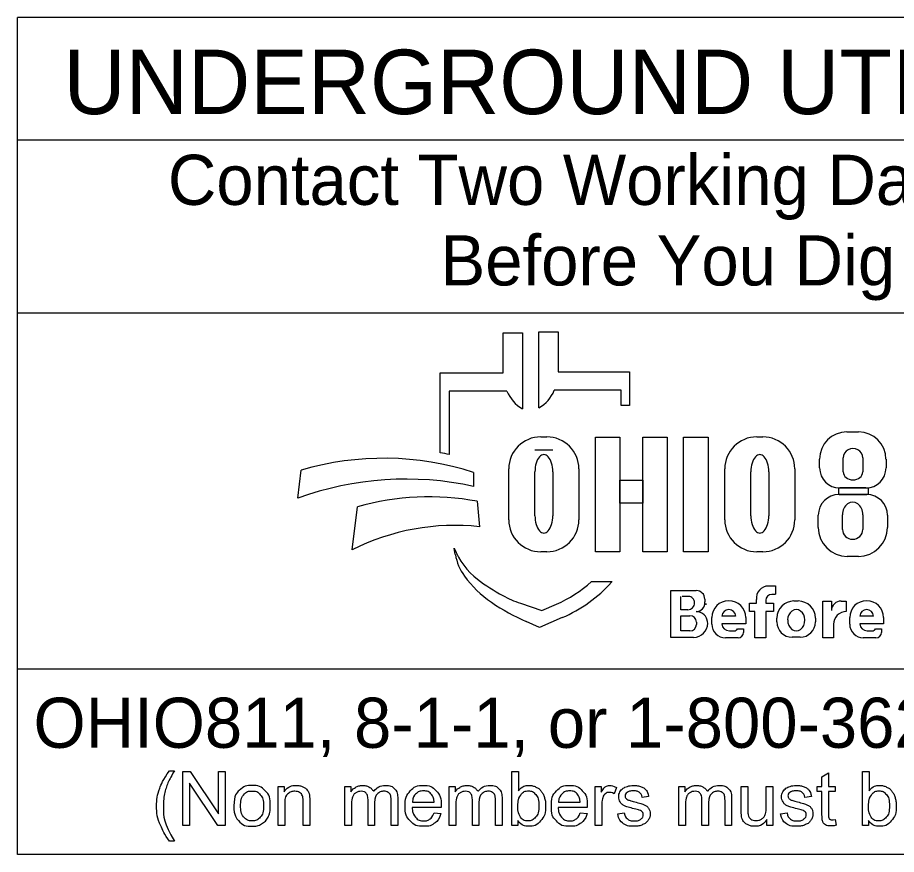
# Model space of a CAD drawing. Extents: x 0 to 34, y -7.5 to 22.
# Drawn here: x 2.378 to 4.831, y 2.143 to 4.48 of the extents above; entities that cross this region are included whole.
import ezdxf

# ---------------------------------------------------------------- set-up
doc = ezdxf.new("R2010")
doc.units = 0
doc.layers.add('SH_Data', color=7, linetype='Continuous')
doc.layers.add('SH_Text', color=7, linetype='Continuous')

msp = doc.modelspace()

# ---------------------------------------------------------------- linework, layer by layer
at = {"layer": 'SH_Data'}
for p, q in [((2.3775, 2.1428), (2.3775, 4.4803)), ((6.6275, 4.4803), (2.3775, 4.4803)), ((2.3775, 4.1387), (6.6275, 4.1387)), ((2.3775, 3.6553), (6.6275, 3.6553)), ((6.6275, 2.6607), (2.3775, 2.6607)), ((6.6275, 2.1428), (2.3775, 2.1428))]:
    msp.add_line(p, q, dxfattribs=at)
at = {"layer": 'SH_Text'}
for p, q in [((3.7335, 3.4883), (3.7335, 3.5998)), ((3.7335, 3.5998), (3.7872, 3.5998)), ((3.7872, 3.5998), (3.7872, 3.3877)), ((3.8329, 3.39), (3.8329, 3.6021)), ((3.8329, 3.6021), (3.8865, 3.6021)), ((3.8865, 3.6021), (3.8865, 3.4906)), ((3.5576, 3.2644), (3.5576, 3.4883)), ((3.5576, 3.4883), (3.7335, 3.4883)), ((3.8865, 3.4906), (4.0857, 3.4906)), ((4.0857, 3.4906), (4.0857, 3.3968)), ((3.5828, 3.4369), (3.5828, 3.26)), ((3.7439, 3.4369), (3.5828, 3.4369)), ((4.0625, 3.4392), (3.8761, 3.4392)), ((4.0625, 3.3968), (4.0625, 3.4392)), ((4.0857, 3.3968), (4.0625, 3.3968)), ((4.6931, 3.3231), (4.7258, 3.3231)), ((3.8385, 3.3091), (3.8551, 3.3091)), ((4.4416, 3.3091), (4.4581, 3.3091)), ((3.8718, 3.2721), (3.822, 3.2721)), ((4.6168, 3.2225), (4.6168, 3.2468)), ((4.683, 3.2111), (4.683, 3.2504)), ((4.7371, 3.2504), (4.7371, 3.2111)), ((4.8022, 3.2468), (4.8022, 3.2225)), ((3.1602, 3.1381), (3.1696, 3.2162)), ((3.7491, 3.0776), (3.7491, 3.2196)), ((3.9445, 3.2196), (3.9445, 3.0776)), ((4.3521, 3.0776), (4.3521, 3.2196)), ((4.5476, 3.2196), (4.5476, 3.0776)), ((3.6509, 3.2097), (3.6509, 3.1709)), ((3.822, 3.089), (3.822, 3.2114)), ((3.8718, 3.2114), (3.8718, 3.089)), ((4.425, 3.089), (4.425, 3.2114)), ((4.4748, 3.2114), (4.4748, 3.089)), ((4.7462, 3.1665), (4.6728, 3.1665)), ((4.671, 3.1482), (4.7483, 3.1482)), ((3.6608, 3.1291), (3.6671, 3.0582)), ((3.312, 2.9936), (3.3267, 3.1137)), ((4.6131, 3.0563), (4.6131, 3.0903)), ((4.6806, 3.0503), (4.6806, 3.0912)), ((4.7374, 3.0912), (4.7374, 3.0503)), ((4.8062, 3.0903), (4.8062, 3.0563)), ((3.5997, 2.9807), (3.5967, 2.9986)), ((3.8551, 2.9882), (3.8385, 2.9882)), ((4.4581, 2.9882), (4.4416, 2.9882)), ((4.7252, 2.9753), (4.6941, 2.9753)), ((3.98, 2.9048), (4.0375, 2.9048)), ((4.2013, 2.749), (4.2013, 2.8798)), ((4.2013, 2.8798), (4.2725, 2.8798)), ((4.4739, 2.8926), (4.4934, 2.8926)), ((4.4934, 2.8926), (4.4934, 2.8696)), ((4.2293, 2.8263), (4.2293, 2.8632)), ((4.2545, 2.8632), (4.2332, 2.8632)), ((4.2963, 2.856), (4.2963, 2.8481)), ((4.4406, 2.8442), (4.4406, 2.8546)), ((4.4667, 2.8526), (4.4667, 2.8442)), ((4.4934, 2.8691), (4.4832, 2.8691)), ((4.5451, 2.8508), (4.5573, 2.8508)), ((4.6254, 2.7478), (4.6254, 2.8505)), ((4.6254, 2.8505), (4.6499, 2.8505)), ((4.6499, 2.8505), (4.6499, 2.8237)), ((4.6772, 2.8505), (4.691, 2.8505)), ((4.691, 2.8505), (4.691, 2.8209)), ((3.7816, 2.8444), (3.841, 2.8239)), ((3.841, 2.8239), (3.8821, 2.8417)), ((4.2487, 2.8263), (4.2293, 2.8263)), ((4.4213, 2.8212), (4.4213, 2.8442)), ((4.4213, 2.8442), (4.4406, 2.8442)), ((4.4667, 2.8442), (4.4883, 2.8442)), ((4.4883, 2.8442), (4.4883, 2.8212)), ((3.8983, 2.8044), (3.835, 2.7769)), ((4.2293, 2.7669), (4.2293, 2.8097)), ((4.2293, 2.8097), (4.2548, 2.8097)), ((4.3159, 2.7858), (4.3159, 2.8042)), ((4.3824, 2.8082), (4.3439, 2.8082)), ((4.4104, 2.8042), (4.4104, 2.7866)), ((4.4362, 2.8212), (4.4213, 2.8212)), ((4.4362, 2.7478), (4.4362, 2.8212)), ((4.4883, 2.8212), (4.4667, 2.8212)), ((4.4667, 2.8212), (4.4667, 2.7478)), ((4.4973, 2.7922), (4.4973, 2.8029)), ((4.6051, 2.8029), (4.6051, 2.7922)), ((4.7008, 2.7858), (4.7008, 2.8042)), ((4.7674, 2.8082), (4.7288, 2.8082)), ((4.7953, 2.8042), (4.7953, 2.7866)), ((3.835, 2.7769), (3.7976, 2.7934)), ((4.2729, 2.7916), (4.2729, 2.7853)), ((4.3043, 2.7887), (4.3043, 2.7884)), ((4.4104, 2.7866), (4.344, 2.7866)), ((4.3876, 2.7729), (4.4045, 2.7729)), ((4.4045, 2.7729), (4.4045, 2.7631)), ((4.6559, 2.786), (4.6559, 2.7478)), ((4.7953, 2.7866), (4.7289, 2.7866)), ((4.7725, 2.7729), (4.7894, 2.7729)), ((4.7894, 2.7729), (4.7894, 2.7631)), ((4.265, 2.749), (4.2013, 2.749)), ((4.2546, 2.7669), (4.2293, 2.7669)), ((4.3649, 2.7673), (4.379, 2.7673)), ((4.5623, 2.7494), (4.5401, 2.7494)), ((4.7498, 2.7673), (4.7639, 2.7673)), ((4.3892, 2.7478), (4.3538, 2.7478)), ((4.4667, 2.7478), (4.4362, 2.7478)), ((4.6559, 2.7478), (4.6254, 2.7478)), ((4.7742, 2.7478), (4.7388, 2.7478))]:
    msp.add_line(p, q, dxfattribs=at)
for points in [[(3.991, 3.3081), (4.0589, 3.3081), (4.0589, 2.9881), (3.991, 2.9881)], [(4.1231, 3.3081), (4.1911, 3.3081), (4.1911, 2.9881), (4.1231, 2.9881)], [(4.2364, 3.3081), (4.3052, 3.3081), (4.3052, 2.9881), (4.2364, 2.9881)], [(4.0589, 3.1882), (4.1231, 3.1882), (4.1231, 3.1242), (4.0589, 3.1242)], [(4.6706, 3.1665), (4.7523, 3.1665), (4.7523, 3.1481), (4.6706, 3.1481)]]:
    msp.add_lwpolyline(points, close=True, dxfattribs=at)
for points in [[(2.8021, 2.3766), (2.8153, 2.3766)], [(2.8389, 2.2239), (2.8389, 2.3741), (2.8592, 2.3741), (2.9382, 2.2561), (2.9382, 2.3741), (2.9572, 2.3741), (2.9572, 2.2239), (2.9369, 2.2239), (2.8579, 2.3419), (2.8579, 2.2239), (2.8389, 2.2239)], [(3.7743, 2.2239), (3.7573, 2.2239), (3.7573, 2.3741), (3.7757, 2.3741), (3.7757, 2.3206)], [(4.6233, 2.2558), (4.6233, 2.3185), (4.6097, 2.3185), (4.6097, 2.3328), (4.6233, 2.3328), (4.6233, 2.3597), (4.6417, 2.3708), (4.6417, 2.3328), (4.6601, 2.3328), (4.6601, 2.3185), (4.6417, 2.3185), (4.6417, 2.2547)], [(4.7534, 2.2239), (4.7363, 2.2239), (4.7363, 2.3741), (4.7548, 2.3741), (4.7548, 2.3206)], [(3.1048, 2.2239), (3.1048, 2.3328), (3.1214, 2.3328), (3.1214, 2.3173)], [(3.2912, 2.2239), (3.2912, 2.3328), (3.3077, 2.3328), (3.3077, 2.3174)], [(3.5826, 2.2239), (3.5826, 2.3328), (3.5991, 2.3328), (3.5991, 2.3174)], [(3.9904, 2.2239), (3.9904, 2.3328), (4.007, 2.3328), (4.007, 2.3163)], [(4.2236, 2.2239), (4.2236, 2.3328), (4.2401, 2.3328), (4.2401, 2.3174)], [(4.3979, 2.2654), (4.3979, 2.3328), (4.4164, 2.3328), (4.4164, 2.2724)], [(4.4676, 2.2745), (4.4676, 2.3328), (4.4861, 2.3328), (4.4861, 2.2239), (4.4696, 2.2239)], [(4.0495, 2.3293), (4.043, 2.3122)], [(3.1233, 2.2833), (3.1233, 2.2239), (3.1048, 2.2239)], [(3.1932, 2.2908), (3.1932, 2.2239), (3.1748, 2.2239), (3.1748, 2.2901)], [(3.3743, 2.2871), (3.3743, 2.2239), (3.3559, 2.2239), (3.3559, 2.2946)], [(3.4388, 2.2986), (3.4388, 2.2239), (3.4203, 2.2239), (3.4203, 2.2924)], [(3.4799, 2.2887), (3.5406, 2.2887)], [(3.6657, 2.2871), (3.6657, 2.2239), (3.6473, 2.2239), (3.6473, 2.2946)], [(3.7301, 2.2986), (3.7301, 2.2239), (3.7117, 2.2239), (3.7117, 2.2924)], [(3.8879, 2.2887), (3.9486, 2.2887)], [(4.1394, 2.3046), (4.1213, 2.3022)], [(4.3067, 2.2871), (4.3067, 2.2239), (4.2883, 2.2239), (4.2883, 2.2946)], [(4.3711, 2.2986), (4.3711, 2.2239), (4.3527, 2.2239), (4.3527, 2.2924)], [(4.594, 2.3046), (4.5759, 2.3022)], [(3.3097, 2.2803), (3.3097, 2.2239), (3.2912, 2.2239)], [(3.56, 2.2736), (3.4788, 2.2736)], [(3.5404, 2.2591), (3.5595, 2.2567)], [(3.601, 2.2803), (3.601, 2.2239), (3.5826, 2.2239)], [(3.968, 2.2736), (3.8868, 2.2736)], [(3.9484, 2.2591), (3.9675, 2.2567)], [(4.0088, 2.2809), (4.0088, 2.2239), (3.9904, 2.2239)], [(4.053, 2.2564), (4.0712, 2.2593)], [(4.242, 2.2803), (4.242, 2.2239), (4.2236, 2.2239)], [(4.5076, 2.2564), (4.5258, 2.2593)], [(3.7743, 2.2375), (3.7743, 2.2239)], [(4.4696, 2.2239), (4.4696, 2.24)], [(4.6601, 2.2404), (4.6628, 2.2241)], [(4.7534, 2.2375), (4.7534, 2.2239)], [(2.8153, 2.1798), (2.8021, 2.1798)]]:
    msp.add_lwpolyline(points, dxfattribs=at)
for centre, radius, start, end in [((3.8353, 3.4736), 0.0985, 201.9296, 240.7469), ((3.7847, 3.476), 0.0985, 299.2531, 338.0704), ((4.6931, 3.2468), 0.0763, 90, 180), ((4.7258, 3.2468), 0.0763, 0, 90), ((3.8385, 3.2196), 0.0895, 90, 180), ((3.8551, 3.2196), 0.0895, 0, 90), ((4.4416, 3.2196), 0.0895, 90, 180), ((4.4581, 3.2196), 0.0895, 0, 90), ((3.4295, 2.4554), 0.8191, 79.2074, 81.0007), ((3.3997, 2.4302), 0.8191, 72.1402, 106.3144), ((4.6728, 3.2225), 0.056, 180, 270), ((4.7462, 3.2225), 0.056, 270, 0), ((3.4628, 2.2991), 0.8919, 77.8238, 109.8274), ((3.5267, 2.4094), 0.7322, 79.44, 105.8467), ((4.671, 3.0903), 0.0579, 90, 180), ((4.7483, 3.0903), 0.0579, 0, 90), ((3.8385, 3.0776), 0.0895, 180, 270), ((3.8551, 3.0776), 0.0895, 270, 0), ((4.4416, 3.0776), 0.0895, 180, 270), ((4.4581, 3.0776), 0.0895, 270, 0), ((3.5987, 2.4262), 0.6357, 83.8248, 116.8021), ((4.6941, 3.0563), 0.081, 180, 270), ((4.7252, 3.0563), 0.081, 270, 0), ((3.7841, 3.0707), 0.2008, 201.0457, 232.5314), ((3.741, 3.0048), 0.1433, 189.6817, 216.0884), ((3.8747, 3.1022), 0.3088, 216.0884, 235.7167), ((3.9766, 3.3219), 0.5173, 232.5314, 241.794), ((3.7387, 3.1722), 0.3602, 293.4582, 312.0712), ((3.7387, 3.1722), 0.401, 293.4582, 317.8286), ((4.2725, 2.856), 0.0238, 0, 90), ((4.4739, 2.859), 0.0335, 90, 187.5187), ((4.0412, 3.3465), 0.6044, 235.7167, 246.2325), ((3.8914, 3.1631), 0.3371, 241.794, 250.9821), ((4.2505, 2.8463), 0.0169, 357.8325, 90), ((4.2721, 2.8453), 0.0243, 270, 6.6529), ((4.3631, 2.8042), 0.0473, 0, 180), ((4.4832, 2.8526), 0.0165, 90, 180), ((4.5451, 2.8029), 0.0478, 90, 180), ((4.5573, 2.8029), 0.0478, 0, 90), ((4.6768, 2.8237), 0.0269, 89.2449, 180), ((4.7481, 2.8042), 0.0473, 0, 180), ((4.2487, 2.845), 0.0187, 270, 2.0582), ((4.2827, 2.8438), 0.0175, 347.4023, 0), ((4.3632, 2.8072), 0.0193, 2.9632, 177.0368), ((4.7481, 2.8072), 0.0193, 2.9632, 177.0368), ((4.2548, 2.7916), 0.0181, 0, 90), ((4.2722, 2.7889), 0.0321, 4.0748, 90), ((4.6908, 2.786), 0.0349, 89.6033, 180), ((4.2546, 2.7853), 0.0184, 270, 0), ((4.265, 2.7884), 0.0393, 270, 0), ((4.2714, 2.7887), 0.033, 0, 11.7502), ((4.3538, 2.7858), 0.038, 180, 270), ((4.3649, 2.7883), 0.021, 184.827, 270), ((4.379, 2.7767), 0.00938, 270, 335.9979), ((4.5401, 2.7922), 0.0428, 180, 270), ((4.5623, 2.7922), 0.0428, 270, 0), ((4.7388, 2.7858), 0.038, 180, 270), ((4.7498, 2.7883), 0.021, 184.827, 270), ((4.7639, 2.7767), 0.00938, 270, 335.9979), ((4.3892, 2.7631), 0.0152, 270, 0), ((4.7742, 2.7631), 0.0152, 270, 0)]:
    msp.add_arc(centre, radius, start, end, dxfattribs=at)
for centre, major_axis, ratio, start_param, end_param in [((4.71, 3.2504), (0.0271, 0), 0.969373, 0, 3.141593), ((3.8469, 3.2114), (0, 0.0484), 0.514403, 4.712389, 7.853982), ((4.4499, 3.2114), (0, 0.0484), 0.514403, 4.712389, 7.853982), ((4.71, 3.2111), (0.0271, 0), 0.818453, 3.141593, 6.283185), ((4.709, 3.0912), (0, 0.0358), 0.794529, 4.712389, 7.853982), ((3.8469, 3.089), (0, 0.0484), 0.514403, 1.570796, 4.712389), ((4.4499, 3.089), (0, 0.0484), 0.514403, 1.570796, 4.712389), ((4.709, 3.0503), (0.0284, 0), 0.959837, 3.141593, 6.283185), ((4.5517, 2.7976), (0, 0.029), 0.832186, 4.712389, 7.853982), ((4.5517, 2.7976), (0, 0.0302), 0.797287, 1.570796, 4.712389)]:
    msp.add_ellipse(centre, major_axis=major_axis, ratio=ratio, start_param=start_param, end_param=end_param, dxfattribs=at)
for points in [[(2.8021, 2.1798), (2.7869, 2.199), (2.7763, 2.2248), (2.7657, 2.2506), (2.7657, 2.2783), (2.7657, 2.3026), (2.7736, 2.325), (2.7829, 2.3509), (2.8021, 2.3766)], [(2.8153, 2.3766), (2.8029, 2.3553), (2.7989, 2.3462), (2.7927, 2.332), (2.7891, 2.3167), (2.7847, 2.2975), (2.7847, 2.2782), (2.7847, 2.2289), (2.8153, 2.1798)], [(2.9814, 2.2783), (2.9814, 2.3085), (2.9981, 2.3231), (3.0122, 2.3352), (3.0323, 2.3352), (3.0547, 2.3352), (3.069, 2.3205), (3.0832, 2.3058), (3.0832, 2.2799), (3.0832, 2.2589), (3.0769, 2.2469), (3.0706, 2.2348), (3.0586, 2.2282), (3.0466, 2.2215), (3.0323, 2.2215), (3.0095, 2.2215), (2.9954, 2.2362), (2.9814, 2.2508), (2.9814, 2.2783)], [(3.1214, 2.3173), (3.1334, 2.3352), (3.156, 2.3352), (3.1659, 2.3352), (3.1741, 2.3316), (3.1823, 2.3281), (3.1864, 2.3224), (3.1905, 2.3166), (3.1922, 2.3087), (3.1932, 2.3036), (3.1932, 2.2908)], [(3.3077, 2.3174), (3.3128, 2.3254), (3.3214, 2.3303), (3.3299, 2.3352), (3.3407, 2.3352), (3.3528, 2.3352), (3.3606, 2.3301), (3.3683, 2.3251), (3.3715, 2.3161), (3.3844, 2.3352), (3.4051, 2.3352), (3.4213, 2.3352), (3.43, 2.3262), (3.4388, 2.3172), (3.4388, 2.2986)], [(3.5595, 2.2567), (3.555, 2.24), (3.5428, 2.2307), (3.5306, 2.2215), (3.5117, 2.2215), (3.4878, 2.2215), (3.4738, 2.2362), (3.4598, 2.2509), (3.4598, 2.2774), (3.4598, 2.3049), (3.474, 2.32), (3.4881, 2.3352), (3.5106, 2.3352), (3.5324, 2.3352), (3.5463, 2.3203), (3.5601, 2.3055), (3.5601, 2.2785), (3.5601, 2.2769), (3.56, 2.2736)], [(3.5991, 2.3174), (3.6042, 2.3254), (3.6127, 2.3303), (3.6212, 2.3352), (3.6321, 2.3352), (3.6442, 2.3352), (3.6519, 2.3301), (3.6597, 2.3251), (3.6628, 2.3161), (3.6758, 2.3352), (3.6965, 2.3352), (3.7127, 2.3352), (3.7214, 2.3262), (3.7301, 2.3172), (3.7301, 2.2986)], [(3.7757, 2.3206), (3.7874, 2.3352), (3.8055, 2.3352), (3.8155, 2.3352), (3.8245, 2.3311), (3.8335, 2.3271), (3.8392, 2.3198), (3.845, 2.3124), (3.8483, 2.3021), (3.8516, 2.2918), (3.8516, 2.28), (3.8516, 2.252), (3.8378, 2.2368), (3.8239, 2.2215), (3.8046, 2.2215), (3.7853, 2.2215), (3.7743, 2.2375)], [(3.9675, 2.2567), (3.963, 2.24), (3.9508, 2.2307), (3.9386, 2.2215), (3.9196, 2.2215), (3.8958, 2.2215), (3.8818, 2.2362), (3.8678, 2.2509), (3.8678, 2.2774), (3.8678, 2.3049), (3.882, 2.32), (3.8961, 2.3352), (3.9186, 2.3352), (3.9404, 2.3352), (3.9543, 2.3203), (3.9681, 2.3055), (3.9681, 2.2785), (3.9681, 2.2769), (3.968, 2.2736)], [(4.007, 2.3163), (4.0133, 2.3278), (4.0187, 2.3315), (4.0241, 2.3352), (4.0305, 2.3352), (4.0398, 2.3352), (4.0495, 2.3293)], [(4.0712, 2.2593), (4.0727, 2.2483), (4.0798, 2.2425), (4.0868, 2.2366), (4.0995, 2.2366), (4.1122, 2.2366), (4.1184, 2.2418), (4.1245, 2.247), (4.1245, 2.254), (4.1245, 2.2602), (4.1191, 2.2638), (4.1153, 2.2663), (4.1002, 2.2701), (4.0799, 2.2752), (4.072, 2.2789), (4.0642, 2.2827), (4.0601, 2.2893), (4.0561, 2.2959), (4.0561, 2.3038), (4.0561, 2.3111), (4.0594, 2.3173), (4.0628, 2.3235), (4.0685, 2.3276), (4.0728, 2.3308), (4.0803, 2.333), (4.0877, 2.3352), (4.0962, 2.3352), (4.109, 2.3352), (4.1187, 2.3315), (4.1284, 2.3278), (4.133, 2.3215), (4.1377, 2.3152), (4.1394, 2.3046)], [(4.2401, 2.3174), (4.2452, 2.3254), (4.2537, 2.3303), (4.2622, 2.3352), (4.2731, 2.3352), (4.2852, 2.3352), (4.2929, 2.3301), (4.3007, 2.3251), (4.3038, 2.3161), (4.3168, 2.3352), (4.3375, 2.3352), (4.3537, 2.3352), (4.3624, 2.3262), (4.3711, 2.3172), (4.3711, 2.2986)], [(4.5258, 2.2593), (4.5273, 2.2483), (4.5343, 2.2425), (4.5414, 2.2366), (4.554, 2.2366), (4.5668, 2.2366), (4.5729, 2.2418), (4.5791, 2.247), (4.5791, 2.254), (4.5791, 2.2602), (4.5736, 2.2638), (4.5698, 2.2663), (4.5548, 2.2701), (4.5345, 2.2752), (4.5266, 2.2789), (4.5188, 2.2827), (4.5147, 2.2893), (4.5107, 2.2959), (4.5107, 2.3038), (4.5107, 2.3111), (4.514, 2.3173), (4.5173, 2.3235), (4.5231, 2.3276), (4.5274, 2.3308), (4.5348, 2.333), (4.5423, 2.3352), (4.5508, 2.3352), (4.5636, 2.3352), (4.5733, 2.3315), (4.583, 2.3278), (4.5876, 2.3215), (4.5922, 2.3152), (4.594, 2.3046)], [(4.7548, 2.3206), (4.7664, 2.3352), (4.7846, 2.3352), (4.7946, 2.3352), (4.8036, 2.3311), (4.8125, 2.3271), (4.8183, 2.3198), (4.8241, 2.3124), (4.8274, 2.3021), (4.8306, 2.2918), (4.8306, 2.28), (4.8306, 2.252), (4.8168, 2.2368), (4.803, 2.2215), (4.7836, 2.2215), (4.7644, 2.2215), (4.7534, 2.2375)], [(3.0003, 2.2783), (3.0003, 2.2574), (3.0094, 2.247), (3.0185, 2.2366), (3.0323, 2.2366), (3.046, 2.2366), (3.0551, 2.2471), (3.0642, 2.2575), (3.0642, 2.279), (3.0642, 2.2991), (3.0551, 2.3095), (3.0459, 2.3199), (3.0323, 2.3199), (3.0185, 2.3199), (3.0094, 2.3096), (3.0003, 2.2992), (3.0003, 2.2783)], [(3.1748, 2.2901), (3.1748, 2.3013), (3.1726, 2.3069), (3.1705, 2.3125), (3.165, 2.3158), (3.1595, 2.3191), (3.1521, 2.3191), (3.1404, 2.3191), (3.1318, 2.3117), (3.1233, 2.3042), (3.1233, 2.2833)], [(3.3559, 2.2946), (3.3559, 2.3069), (3.3514, 2.313), (3.3469, 2.3191), (3.3366, 2.3191), (3.3288, 2.3191), (3.3222, 2.315), (3.3156, 2.311), (3.3126, 2.3031), (3.3097, 2.2952), (3.3097, 2.2803)], [(3.4203, 2.2924), (3.4203, 2.3035), (3.4185, 2.3083), (3.4168, 2.3132), (3.412, 2.3162), (3.4073, 2.3191), (3.401, 2.3191), (3.3895, 2.3191), (3.3819, 2.3115), (3.3743, 2.3039), (3.3743, 2.2871)], [(3.5406, 2.2887), (3.5394, 2.3025), (3.5337, 2.3094), (3.5249, 2.3201), (3.5108, 2.3201), (3.4981, 2.3201), (3.4894, 2.3115), (3.4808, 2.303), (3.4799, 2.2887)], [(3.6473, 2.2946), (3.6473, 2.3069), (3.6428, 2.313), (3.6383, 2.3191), (3.628, 2.3191), (3.6202, 2.3191), (3.6136, 2.315), (3.607, 2.311), (3.604, 2.3031), (3.601, 2.2952), (3.601, 2.2803)], [(3.7117, 2.2924), (3.7117, 2.3035), (3.7099, 2.3083), (3.7081, 2.3132), (3.7034, 2.3162), (3.6987, 2.3191), (3.6923, 2.3191), (3.6809, 2.3191), (3.6733, 2.3115), (3.6657, 2.3039), (3.6657, 2.2871)], [(3.7741, 2.2792), (3.7741, 2.2596), (3.7794, 2.2509), (3.7881, 2.2366), (3.8029, 2.2366), (3.815, 2.2366), (3.8238, 2.2471), (3.8326, 2.2576), (3.8326, 2.2784), (3.8326, 2.2998), (3.8241, 2.3099), (3.8157, 2.3201), (3.8038, 2.3201), (3.7917, 2.3201), (3.7829, 2.3096), (3.7741, 2.299), (3.7741, 2.2792)], [(3.9486, 2.2887), (3.9474, 2.3025), (3.9417, 2.3094), (3.9328, 2.3201), (3.9188, 2.3201), (3.9061, 2.3201), (3.8974, 2.3115), (3.8888, 2.303), (3.8879, 2.2887)], [(4.043, 2.3122), (4.0363, 2.3162), (4.0295, 2.3162), (4.0235, 2.3162), (4.0187, 2.3125), (4.0139, 2.3089), (4.0119, 2.3024), (4.0088, 2.2926), (4.0088, 2.2809)], [(4.1213, 2.3022), (4.1201, 2.3106), (4.1142, 2.3153), (4.1083, 2.3201), (4.0975, 2.3201), (4.0848, 2.3201), (4.0794, 2.3159), (4.0739, 2.3116), (4.0739, 2.306), (4.0739, 2.3024), (4.0762, 2.2995), (4.0785, 2.2966), (4.0833, 2.2946), (4.086, 2.2936), (4.0996, 2.2899), (4.1192, 2.2847), (4.1269, 2.2813), (4.1347, 2.278), (4.1391, 2.2717), (4.1435, 2.2653), (4.1435, 2.2559), (4.1435, 2.2467), (4.1381, 2.2386), (4.1327, 2.2304), (4.1226, 2.226), (4.1124, 2.2215), (4.0996, 2.2215), (4.0784, 2.2215), (4.0672, 2.2303), (4.0561, 2.2391), (4.053, 2.2564)], [(4.2883, 2.2946), (4.2883, 2.3069), (4.2838, 2.313), (4.2793, 2.3191), (4.269, 2.3191), (4.2612, 2.3191), (4.2546, 2.315), (4.248, 2.311), (4.245, 2.3031), (4.242, 2.2952), (4.242, 2.2803)], [(4.3527, 2.2924), (4.3527, 2.3035), (4.3509, 2.3083), (4.3491, 2.3132), (4.3444, 2.3162), (4.3397, 2.3191), (4.3333, 2.3191), (4.3219, 2.3191), (4.3143, 2.3115), (4.3067, 2.3039), (4.3067, 2.2871)], [(4.5759, 2.3022), (4.5747, 2.3106), (4.5688, 2.3153), (4.5629, 2.3201), (4.5521, 2.3201), (4.5394, 2.3201), (4.5339, 2.3159), (4.5285, 2.3116), (4.5285, 2.306), (4.5285, 2.3024), (4.5308, 2.2995), (4.533, 2.2966), (4.5378, 2.2946), (4.5406, 2.2936), (4.5542, 2.2899), (4.5737, 2.2847), (4.5815, 2.2813), (4.5893, 2.278), (4.5937, 2.2717), (4.5981, 2.2653), (4.5981, 2.2559), (4.5981, 2.2467), (4.5927, 2.2386), (4.5873, 2.2304), (4.5772, 2.226), (4.567, 2.2215), (4.5542, 2.2215), (4.5329, 2.2215), (4.5218, 2.2303), (4.5107, 2.2391), (4.5076, 2.2564)], [(4.7532, 2.2792), (4.7532, 2.2596), (4.7585, 2.2509), (4.7672, 2.2366), (4.782, 2.2366), (4.7941, 2.2366), (4.8029, 2.2471), (4.8116, 2.2576), (4.8116, 2.2784), (4.8116, 2.2998), (4.8032, 2.3099), (4.7948, 2.3201), (4.7828, 2.3201), (4.7708, 2.3201), (4.762, 2.3096), (4.7532, 2.299), (4.7532, 2.2792)], [(3.4788, 2.2736), (3.4799, 2.2557), (3.489, 2.2462), (3.4981, 2.2366), (3.5117, 2.2366), (3.5219, 2.2366), (3.5291, 2.242), (3.5362, 2.2473), (3.5404, 2.2591)], [(3.8868, 2.2736), (3.8879, 2.2557), (3.897, 2.2462), (3.9061, 2.2366), (3.9197, 2.2366), (3.9299, 2.2366), (3.937, 2.242), (3.9442, 2.2473), (3.9484, 2.2591)], [(4.4696, 2.24), (4.4569, 2.2215), (4.4351, 2.2215), (4.4255, 2.2215), (4.4171, 2.2252), (4.4088, 2.2289), (4.4047, 2.2345), (4.4007, 2.2401), (4.3991, 2.2482), (4.3979, 2.2536), (4.3979, 2.2654)], [(4.4164, 2.2724), (4.4164, 2.258), (4.4175, 2.253), (4.4192, 2.2457), (4.4249, 2.2416), (4.4305, 2.2374), (4.4388, 2.2374), (4.4471, 2.2374), (4.4543, 2.2417), (4.4616, 2.2459), (4.4646, 2.2533), (4.4676, 2.2606), (4.4676, 2.2745)], [(4.6628, 2.2241), (4.655, 2.2224), (4.6488, 2.2224), (4.6388, 2.2224), (4.6333, 2.2256), (4.6278, 2.2288), (4.6255, 2.234), (4.6233, 2.2392), (4.6233, 2.2558)], [(4.6417, 2.2547), (4.6417, 2.2468), (4.6427, 2.2445), (4.6436, 2.2423), (4.6458, 2.2409), (4.648, 2.2396), (4.6521, 2.2396), (4.6551, 2.2396), (4.6601, 2.2404)]]:
    msp.add_open_spline(points, degree=3, dxfattribs=at)

# ---------------------------------------------------------------- texts
for s, height, p in [('UNDERGROUND UTILITIES', 0.18, (2.5057, 4.2106)), ('Contact Two Working Days', 0.14, (2.7972, 3.9571)), ('Before You Dig', 0.14, (3.5583, 3.7321)), ('OHIO811, 8-1-1, or 1-800-362-2764', 0.14, (2.422, 2.4406))]:
    msp.add_text(s, height=height, dxfattribs=at).set_placement(p)

doc.saveas('drawing.dxf')
